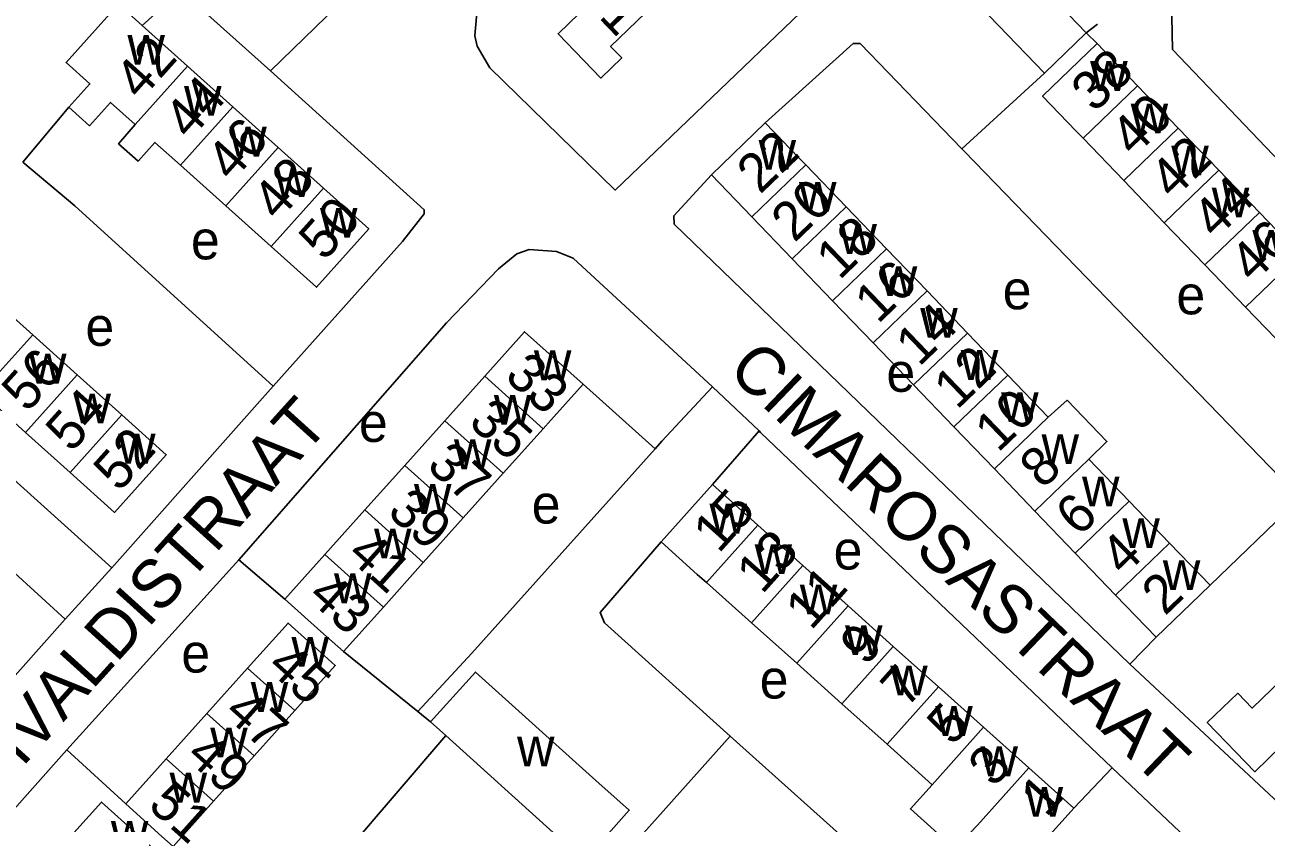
# Model space of a CAD drawing. Extents: x 159045 to 160918, y 380454 to 382516.
# Drawn here: x 159441.1 to 159569.2, y 382048.4 to 382130.8 of the extents above; entities that cross this region are included whole.
import ezdxf

# ---------------------------------------------------------------- set-up
doc = ezdxf.new("R2010")
doc.units = 0
for name, color, linetype in [('BLT_Basislijn', 7, 'Continuous'), ('BLT_Bebouwing', 7, 'Continuous'), ('BLT_Centroide', 7, 'Continuous'), ('BLT_Huisnummer', 7, 'Continuous'), ('BLT_Huisnummer_ tussenligend', 7, 'Continuous'), ('BLT_Onderverdeling_panden', 7, 'Continuous'), ('BLT_Straatnaam', 7, 'Continuous')]:
    doc.layers.add(name, color=color, linetype=linetype)

msp = doc.modelspace()

# ---------------------------------------------------------------- linework, layer by layer
at = {"layer": 'BLT_Basislijn'}
for p, q in [((159559.41, 382133.29), (159559.51, 382128.24)), ((159473.33, 382132.75), (159466.42, 382126.03)), ((159551.76, 382130.85), (159550.62, 382129.96)), ((159550.62, 382129.96), (159551.73, 382128.84)), ((159587.21, 382099.23), (159559.51, 382128.24)), ((159537.79, 382117.98), (159546.29, 382125.8)), ((159445.62, 382122.3), (159440.87, 382116.62)), ((159450.05, 382074.76), (159424.31, 382097.97)), ((159450.05, 382074.76), (159466.71, 382093.52)), ((159506.11, 382087.04), (159498.7, 382093.71)), ((159512.03, 382093.44), (159516.84, 382088.9)), ((159512.05, 382083.36), (159516.84, 382088.9)), ((159572.69, 382081.95), (159563.39, 382072.97)), ((159463.17, 382075.58), (159445.41, 382056.01)), ((159463.17, 382075.58), (159467.9, 382071.55)), ((159445.22, 382069.48), (159450.05, 382074.76)), ((159445.22, 382069.48), (159428.38, 382050.54)), ((159557.83, 382067.62), (159555.1, 382064.83)), ((159481.62, 382059.94), (159473.94, 382066.13)), ((159482.94, 382058.87), (159481.62, 382059.94)), ((159466.74, 382036.77), (159484.51, 382057.46)), ((159504.93, 382047.4), (159513.87, 382057.42)), ((159513.87, 382057.42), (159537.25, 382036.45)), ((159451.48, 382050.41), (159445.41, 382056.01)), ((159553.28, 382054.14), (159549.34, 382049.98))]:
    msp.add_line(p, q, dxfattribs=at)
for points in [[(159518.37, 382163.2), (159490.66, 382137.2), (159487.86, 382133.59), (159487.51, 382129.65), (159487.74, 382128.59), (159489.07, 382126.36), (159502, 382113.74), (159531.07, 382141.61)], [(159466.42, 382126.03), (159457.06, 382134.43), (159455.49, 382132.78), (159453.19, 382130.71)], [(159517.49, 382120.68), (159526.56, 382128.85), (159527.29, 382128.84), (159537.79, 382117.98)], [(159466.71, 382093.52), (159480.05, 382108.42), (159482.29, 382111.3), (159482.29, 382111.71), (159466.42, 382126.03)], [(159537.79, 382117.98), (159538.06, 382117.7), (159572.69, 382081.95)], [(159466.71, 382093.52), (159446.24, 382112.11), (159440.87, 382116.62)], [(159511.93, 382115.32), (159508.05, 382111.08), (159508.1, 382110.22), (159555.1, 382064.83)], [(159512.03, 382093.44), (159497.65, 382106.72), (159495.94, 382107.39), (159493.11, 382107.61), (159491.83, 382107.16), (159489.94, 382105.62), (159484.58, 382100.04), (159463.17, 382075.58)], [(159445.22, 382069.48), (159419.61, 382092.85), (159419.49, 382092.97)], [(159506.11, 382087.04), (159506.81, 382087.82), (159512.03, 382093.44)], [(159516.84, 382088.9), (159517.01, 382088.74), (159553.28, 382054.14)], [(159481.62, 382059.94), (159487.2, 382065.97), (159506.11, 382087.04)], [(159506.75, 382077.44), (159500.45, 382070.18), (159500.9, 382069.1), (159513.87, 382057.42)], [(159555.1, 382064.83), (159574.59, 382046.67), (159575.54, 382046.31), (159577.33, 382046.24), (159578.82, 382046.51), (159580.88, 382047.53), (159605.07, 382073.38)], [(159445.41, 382056.01), (159420.6, 382028.1), (159419.67, 382026.94)], [(159547.64, 382011.18), (159569.75, 382036.02), (159569.64, 382038.11), (159569.12, 382039.17), (159553.28, 382054.14)]]:
    msp.add_lwpolyline(points, dxfattribs=at)
at = {"layer": 'BLT_Bebouwing'}
for p, q in [((159537.57, 382143.52), (159550.62, 382129.96)), ((159546.29, 382125.8), (159531.07, 382141.61)), ((159453.19, 382130.71), (159457.86, 382126.52)), ((159550.62, 382129.96), (159546.29, 382125.8)), ((159551.73, 382128.84), (159555.92, 382124.49)), ((159457.86, 382126.52), (159462.54, 382122.32)), ((159555.92, 382124.49), (159560.11, 382120.14)), ((159462.54, 382122.32), (159467.21, 382118.12)), ((159511.93, 382115.32), (159517.49, 382120.68)), ((159550.3, 382119.08), (159554.48, 382114.72)), ((159560.11, 382120.14), (159564.29, 382115.78)), ((159467.21, 382118.12), (159471.89, 382113.93)), ((159461.81, 382112.1), (159457.14, 382116.3)), ((159516.1, 382110.99), (159511.93, 382115.32)), ((159521.66, 382116.34), (159525.84, 382112)), ((159564.29, 382115.78), (159568.48, 382111.43)), ((159554.48, 382114.72), (159558.67, 382110.37)), ((159466.49, 382107.91), (159461.81, 382112.1)), ((159525.84, 382112), (159530.01, 382107.67)), ((159568.48, 382111.43), (159572.67, 382107.08)), ((159520.27, 382106.65), (159516.1, 382110.99)), ((159558.67, 382110.37), (159562.85, 382106.02)), ((159530.01, 382107.67), (159534.18, 382103.33)), ((159524.44, 382102.31), (159520.27, 382106.65)), ((159562.85, 382106.02), (159567.04, 382101.67)), ((159437.28, 382102.93), (159441.88, 382098.81)), ((159534.18, 382103.33), (159538.35, 382098.99)), ((159528.62, 382097.98), (159524.44, 382102.31)), ((159567.04, 382101.67), (159571.23, 382097.32)), ((159441.88, 382098.81), (159446.47, 382094.68)), ((159538.35, 382098.99), (159542.53, 382094.66)), ((159532.79, 382093.64), (159528.62, 382097.98)), ((159446.47, 382094.68), (159451.07, 382090.56)), ((159484.4, 382089.94), (159488.53, 382094.54)), ((159536.96, 382089.3), (159532.79, 382093.64)), ((159542.53, 382094.66), (159546.7, 382090.32)), ((159441.13, 382088.73), (159436.54, 382092.86)), ((159480.27, 382085.34), (159484.4, 382089.94)), ((159445.73, 382084.61), (159441.13, 382088.73)), ((159494.57, 382089.11), (159490.45, 382084.52)), ((159541.13, 382084.97), (159536.96, 382089.3)), ((159550.87, 382085.99), (159555.04, 382081.65)), ((159476.15, 382080.75), (159480.27, 382085.34)), ((159490.45, 382084.52), (159486.32, 382079.92)), ((159545.31, 382080.63), (159541.13, 382084.97)), ((159512.05, 382083.36), (159506.75, 382077.44)), ((159516.71, 382079.18), (159512.05, 382083.36)), ((159472.02, 382076.15), (159476.15, 382080.75)), ((159555.04, 382081.65), (159559.22, 382077.31)), ((159486.32, 382079.92), (159482.19, 382075.32)), ((159549.48, 382076.29), (159545.31, 382080.63)), ((159521.37, 382075.01), (159516.71, 382079.18)), ((159559.22, 382077.31), (159563.39, 382072.97)), ((159467.9, 382071.55), (159472.02, 382076.15)), ((159553.65, 382071.96), (159549.48, 382076.29)), ((159482.19, 382075.32), (159478.07, 382070.72)), ((159526.03, 382070.84), (159521.37, 382075.01)), ((159511.41, 382073.26), (159516.07, 382069.09)), ((159557.83, 382067.62), (159553.65, 382071.96)), ((159478.07, 382070.72), (159473.94, 382066.13)), ((159530.69, 382066.67), (159526.03, 382070.84)), ((159516.07, 382069.09), (159520.73, 382064.92)), ((159535.36, 382062.49), (159530.69, 382066.67)), ((159459.86, 382059.74), (159464.05, 382064.41)), ((159520.73, 382064.92), (159525.4, 382060.75)), ((159540.02, 382058.32), (159535.36, 382062.49)), ((159525.4, 382060.75), (159530.06, 382056.57)), ((159455.67, 382055.08), (159459.86, 382059.74)), ((159468.92, 382060.04), (159464.73, 382055.37)), ((159482.94, 382058.87), (159484.51, 382057.46)), ((159544.68, 382054.15), (159540.02, 382058.32)), ((159484.51, 382057.46), (159498.82, 382044.57)), ((159530.06, 382056.57), (159534.72, 382052.4)), ((159451.48, 382050.41), (159455.67, 382055.08)), ((159464.73, 382055.37), (159460.55, 382050.7)), ((159549.34, 382049.98), (159544.68, 382054.15)), ((159460.55, 382050.7), (159456.36, 382046.04))]:
    msp.add_line(p, q, dxfattribs=at)
for points in [[(159500.48, 382138.37), (159500, 382137.91), (159496.12, 382134.17), (159498.27, 382131.94), (159496.11, 382129.86), (159500.52, 382125.29), (159502.68, 382127.37), (159501.53, 382128.56), (159505.13, 382132.03), (159505.89, 382132.76)], [(159445.62, 382122.3), (159447.79, 382124.69), (159445.33, 382126.9), (159450.73, 382132.92), (159453.19, 382130.71)], [(159551.73, 382128.84), (159546.11, 382123.43), (159549.58, 382119.82), (159550.3, 382119.08)], [(159452.46, 382120.5), (159449.92, 382122.78), (159447.75, 382120.37), (159445.62, 382122.3)], [(159457.14, 382116.3), (159454.5, 382118.66), (159452.75, 382116.72), (159450.75, 382118.52), (159452.46, 382120.5)], [(159517.49, 382120.68), (159520.96, 382117.07), (159521.66, 382116.34)], [(159471.89, 382113.93), (159476.57, 382109.73), (159471.16, 382103.71), (159466.49, 382107.91)], [(159488.53, 382094.54), (159492.65, 382099.13), (159498.7, 382093.71)], [(159498.7, 382093.71), (159495.36, 382089.99), (159494.57, 382089.11)], [(159546.7, 382090.32), (159548.65, 382092.05), (159552.74, 382087.79), (159550.87, 382085.99)], [(159451.07, 382090.56), (159455.66, 382086.44), (159450.32, 382080.49), (159445.73, 382084.61)], [(159506.75, 382077.44), (159510.47, 382074.1), (159511.41, 382073.26)], [(159563.39, 382072.97), (159561.43, 382071.08), (159557.83, 382067.62)], [(159473.94, 382066.13), (159471.62, 382068.21), (159467.9, 382071.55)], [(159464.05, 382064.41), (159468.24, 382069.08), (159471.96, 382065.74), (159473.11, 382064.71), (159468.92, 382060.04)], [(159498.82, 382044.57), (159500, 382045.88), (159503.44, 382049.77), (159500, 382052.84), (159487.58, 382064.02), (159482.94, 382058.87)], [(159571.81, 382064.22), (159567.74, 382060.3), (159566.27, 382061.84), (159563.11, 382058.8), (159568, 382053.73), (159570.85, 382056.47), (159572.82, 382054.42), (159577.19, 382058.63)], [(159534.72, 382052.4), (159532.46, 382049.9), (159537.05, 382045.79), (159539.38, 382048.23)], [(159450.91, 382040.58), (159455.03, 382045.16), (159452.7, 382047.25), (159448.97, 382050.6), (159444.85, 382046.01)], [(159456.36, 382046.04), (159455.2, 382047.07), (159451.48, 382050.41)], [(159544.04, 382044.06), (159546, 382046.25), (159549.34, 382049.98)]]:
    msp.add_lwpolyline(points, dxfattribs=at)
at = {"layer": 'BLT_Onderverdeling_panden'}
for p, q in [((159452.46, 382120.5), (159457.86, 382126.52)), ((159550.3, 382119.08), (159555.92, 382124.49)), ((159457.14, 382116.3), (159462.54, 382122.32)), ((159554.48, 382114.72), (159560.11, 382120.14)), ((159461.81, 382112.1), (159467.21, 382118.12)), ((159516.1, 382110.99), (159521.66, 382116.34)), ((159558.67, 382110.37), (159564.29, 382115.78)), ((159466.49, 382107.91), (159471.89, 382113.93)), ((159520.27, 382106.65), (159525.84, 382112)), ((159562.85, 382106.02), (159568.48, 382111.43)), ((159524.44, 382102.31), (159530.01, 382107.67)), ((159567.04, 382101.67), (159572.67, 382107.08)), ((159528.62, 382097.98), (159534.18, 382103.33)), ((159436.54, 382092.86), (159441.88, 382098.81)), ((159532.79, 382093.64), (159538.35, 382098.99)), ((159441.13, 382088.73), (159446.47, 382094.68)), ((159494.57, 382089.11), (159488.53, 382094.54)), ((159536.96, 382089.3), (159542.53, 382094.66)), ((159445.73, 382084.61), (159451.07, 382090.56)), ((159490.45, 382084.52), (159484.4, 382089.94)), ((159541.13, 382084.97), (159546.7, 382090.32)), ((159545.31, 382080.63), (159550.87, 382085.99)), ((159486.32, 382079.92), (159480.27, 382085.34)), ((159482.19, 382075.32), (159476.15, 382080.75)), ((159549.48, 382076.29), (159555.04, 382081.65)), ((159511.41, 382073.26), (159516.71, 382079.18)), ((159553.65, 382071.96), (159559.22, 382077.31)), ((159478.07, 382070.72), (159472.02, 382076.15)), ((159516.07, 382069.09), (159521.37, 382075.01)), ((159520.73, 382064.92), (159526.03, 382070.84)), ((159525.4, 382060.75), (159530.69, 382066.67)), ((159468.92, 382060.04), (159464.05, 382064.41)), ((159530.06, 382056.57), (159535.36, 382062.49)), ((159464.73, 382055.37), (159459.86, 382059.74)), ((159534.72, 382052.4), (159540.02, 382058.32)), ((159460.55, 382050.7), (159455.67, 382055.08)), ((159539.38, 382048.23), (159544.68, 382054.15))]:
    msp.add_line(p, q, dxfattribs=at)

# ---------------------------------------------------------------- texts
at = {"layer": 'BLT_Centroide'}
for s, p in [('w', (159451.66, 382126.66)), ('w', (159551.02, 382123.97)), ('w', (159457.5, 382121.41)), ('w', (159555.2, 382119.59)), ('w', (159462.17, 382117.2)), ('w', (159516.8, 382115.84)), ('w', (159559.39, 382115.25)), ('w', (159466.84, 382113.02)), ('w', (159520.97, 382111.5)), ('w', (159563.57, 382110.91)), ('w', (159471.53, 382108.83)), ('w', (159525.14, 382107.16)), ('e', (159458.21, 382106.59)), ('w', (159567.76, 382106.56)), ('w', (159529.31, 382102.81)), ('e', (159541.99, 382101.44)), ('e', (159559.92, 382100.92)), ('w', (159533.48, 382098.5)), ('e', (159447.32, 382097.67)), ('w', (159441.5, 382093.78)), ('w', (159493.61, 382094.12)), ('e', (159529.99, 382092.93)), ('w', (159537.66, 382094.16)), ('w', (159446.09, 382089.66)), ('w', (159489.48, 382089.53)), ('w', (159541.83, 382089.81)), ('e', (159475.55, 382087.76)), ('w', (159450.69, 382085.53)), ('w', (159546, 382085.47)), ('w', (159485.36, 382084.94)), ('w', (159481.23, 382080.34)), ('w', (159550.18, 382081.12)), ('e', (159493.38, 382079.34)), ('w', (159511.73, 382078.31)), ('w', (159554.34, 382076.81)), ('w', (159477.11, 382075.75)), ('w', (159516.39, 382074.14)), ('e', (159524.54, 382074.6)), ('w', (159558.52, 382072.47)), ('w', (159472.98, 382071.12)), ('w', (159521.05, 382069.97)), ('w', (159525.72, 382065.78)), ('e', (159457.22, 382063.97)), ('w', (159468.59, 382064.56)), ('e', (159516.91, 382061.29)), ('w', (159530.38, 382061.62)), ('w', (159464.39, 382059.91)), ('w', (159535.03, 382057.44)), ('w', (159460.2, 382055.22)), ('w', (159491.87, 382054.28)), ('w', (159539.7, 382053.28)), ('w', (159456.01, 382050.56)), ('w', (159544.36, 382049.09)), ('w', (159449.95, 382045.59))]:
    msp.add_text(s, height=4, dxfattribs=at).set_placement(p)
at = {"layer": 'BLT_Huisnummer'}
for s, rotation, p in [('31', 313.9774, (159498.14, 382133.7)), ('42', 48.0928, (159452.99, 382122.88)), ('38', 43.8887, (159551.46, 382121.64)), ('46', 48.0881, (159462.44, 382114.48)), ('22', 43.8981, (159516.95, 382113.23)), ('42', 43.8885, (159559.56, 382112.65)), ('50', 48.0976, (159471.98, 382106.31)), ('18', 43.8979, (159525.13, 382104.37)), ('46', 43.8881, (159567.83, 382104.02)), ('14', 43.8977, (159533.35, 382095.43)), ('56', 48.0932, (159441.32, 382090.69)), ('33', 318.0951, (159490.45, 382094.36)), ('10', 43.8975, (159541.51, 382086.58)), ('52', 48.0921, (159450.8, 382082.49)), ('37', 318.0946, (159482.4, 382085.12)), ('15', 48.1688, (159512.68, 382076.16)), ('6', 43.8973, (159549.86, 382077.89)), ('41', 318.0886, (159474.18, 382075.92)), ('2', 43.89, (159558.73, 382069.74)), ('9', 48.1694, (159527.84, 382064.54)), ('45', 318.0947, (159465.91, 382064.38)), ('5', 48.1699, (159536.81, 382056.31)), ('49', 318.1048, (159457.54, 382055.16)), ('1', 48.1704, (159546.47, 382048.95))]:
    msp.add_text(s, height=4, rotation=rotation, dxfattribs=at).set_placement(p)
at = {"layer": 'BLT_Huisnummer_ tussenligend'}
for s, rotation, p in [('44', 48.0928, (159458.07, 382118.8)), ('40', 43.8887, (159555.52, 382117.05)), ('48', 48.0881, (159467.2, 382110.41)), ('20', 43.8979, (159520.5, 382108.24)), ('44', 43.8885, (159563.96, 382108.57)), ('16', 43.8977, (159529.11, 382099.85)), ('12', 43.8975, (159537.27, 382091)), ('54', 48.0921, (159445.87, 382086.56)), ('35', 318.0951, (159486.72, 382089.61)), ('8', 43.8973, (159546.13, 382082.81)), ('39', 318.0946, (159478.34, 382080.36)), ('13', 48.1694, (159517.16, 382071.95)), ('4', 43.89, (159554.48, 382073.8)), ('11', 48.1694, (159522.21, 382068.22)), ('43', 318.0886, (159470.12, 382071.63)), ('7', 48.1699, (159532.05, 382060.2)), ('47', 318.0947, (159461.49, 382059.63)), ('3', 48.1704, (159541.08, 382052.01)), ('51', 318.1048, (159453.64, 382050.1))]:
    msp.add_text(s, height=4, rotation=rotation, dxfattribs=at).set_placement(p)
at = {"layer": 'BLT_Straatnaam'}
for s, height, rotation, p in [('CIMAROSASTRAAT', 4.9999, 316.1846, (159513.45, 382095)), ('VIVALDISTRAAT', 5, 47.8952, (159437.81, 382050.82)), ('MENDELSSOHNLAAN', 5, 47.606, (159559.9, 382010.56))]:
    msp.add_text(s, height=height, rotation=rotation, dxfattribs=at).set_placement(p)

doc.saveas('drawing.dxf')
